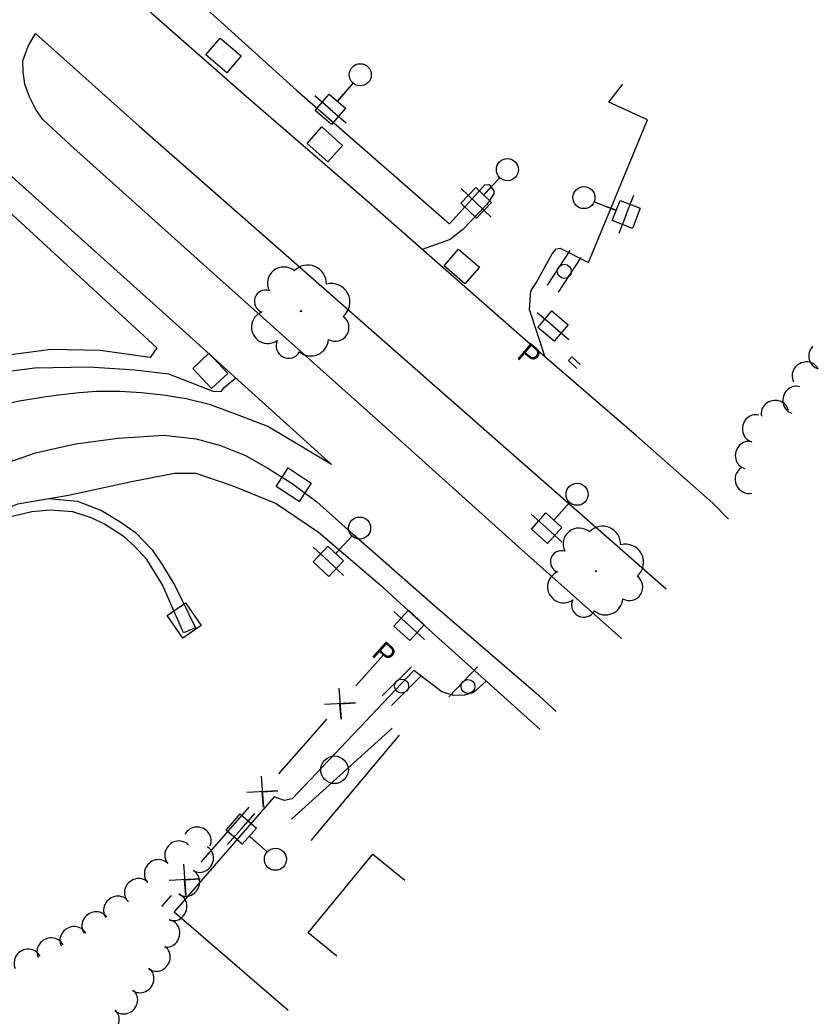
# Model space of a CAD drawing. Extents: x 1746010 to 1754829, y 655801 to 663091.
# Drawn here: x 1754540 to 1754828.9, y 656558.2 to 656918.7 of the extents above; entities that cross this region are included whole.
import ezdxf

# ---------------------------------------------------------------- set-up
doc = ezdxf.new("R2010")
doc.units = 0
for name, color, linetype in [('SURVEY - AERIAL SURVEY - Photo Control - Points - Elevations', 7, 'Continuous'), ('SURVEY - AERIAL SURVEY - Photo Control - Points - Locators', 7, 'Continuous'), ('SURVEY - AERIAL SURVEY - Photo Control with Text', 7, 'Continuous'), ('SURVEY - CENTERLINE - Existing Roads - Development', 7, 'Continuous'), ('SURVEY - CENTERLINE - Existing Roads Curve Text', 7, 'Continuous'), ('SURVEY - CENTERLINE - Existing Roads Text', 7, 'Continuous'), ('SURVEY - CENTERLINE - Preliminary - Development', 7, 'Continuous')]:
    doc.layers.add(name, color=color, linetype=linetype)

msp = doc.modelspace()

# ---------------------------------------------------------------- linework, layer by layer
at = {"layer": 'SURVEY - AERIAL SURVEY - Photo Control - Points - Elevations'}
for points in [[(1754741.64, 656792.56), (1754738.61, 656795.45), (1754739.83, 656796.72), (1754742.83, 656793.98)], [(1754550.39, 656745.47), (1754560.92, 656744.56), (1754569.61, 656741.2), (1754576.59, 656737.01), (1754581.85, 656733.17), (1754587.85, 656726.9), (1754591.59, 656721.34), (1754596.16, 656714.07), (1754603.59, 656698.7), (1754599.27, 656696.86), (1754591.65, 656714.3), (1754585.99, 656723.46), (1754581.44, 656728.39), (1754577.71, 656731.61), (1754570.64, 656736.24), (1754566.2, 656738.38), (1754559.15, 656740.67), (1754551.03, 656741.33), (1754544.35, 656740.64), (1754535.62, 656738.59)]]:
    msp.add_lwpolyline(points, dxfattribs=at)
at = {"layer": 'SURVEY - AERIAL SURVEY - Photo Control - Points - Locators'}
for points in [[(1754796.56, 656738.08), (1754790.79, 656743.77), (1754763.21, 656768.22), (1754722.88, 656802.95), (1754666.41, 656852.52), (1754621.07, 656891.69), (1754588.26, 656920.54), (1754581.81, 656926.89), (1754576.84, 656932.85), (1754573.4, 656937.61), (1754569.31, 656945.5), (1754567.71, 656950.42), (1754566.71, 656958.02), (1754566.56, 656966.03), (1754567.44, 656980.31), (1754571.26, 657001.16), (1754577.86, 657026.55), (1754586.05, 657050.51), (1754591.49, 657064.7), (1754606.23, 657097.49), (1754608.53, 657102.38)], [(1754566.62, 656967.04), (1754578.1, 656974.24), (1754587.27, 656976.38), (1754597.53, 656965.39), (1754600.9, 656960.46), (1754602.11, 656955.79), (1754601.33, 656951.64), (1754599.11, 656947.66), (1754590.27, 656938.32), (1754640.23, 656893.15), (1754695.52, 656844.87), (1754708.29, 656859.01), (1754709.91, 656859.11), (1754711.54, 656856.88), (1754711.55, 656855.7), (1754709.06, 656851.9), (1754700.4, 656842.83), (1754695.74, 656839.29), (1754685.63, 656835.65)], [(1754757.83, 656694.9), (1754721.68, 656726.94), (1754671.32, 656772.3), (1754610.07, 656826.93), (1754558.32, 656873.39), (1754548.36, 656882.63), (1754545.73, 656886.28), (1754543.51, 656890.83), (1754541.86, 656895.38), (1754541.15, 656899.9), (1754541.03, 656903.83), (1754542.96, 656909.13), (1754545.61, 656913.76), (1754583.25, 656880.21), (1754650.13, 656821.51), (1754710.03, 656768.93), (1754773.93, 656712.85)], [(1754730.17, 656796.68), (1754724.48, 656813.85), (1754724.97, 656820.52), (1754726.93, 656823.5), (1754732.7, 656834.08), (1754734.22, 656835.8), (1754735.56, 656836.08), (1754745.78, 656830.94), (1754767.17, 656882.52), (1754753.16, 656888.98), (1754758.28, 656895.43)], [(1754491.26, 656782.28), (1754505.51, 656831.98), (1754517.14, 656872.99), (1754517.76, 656873.93), (1754518.56, 656874.56), (1754520.31, 656874.58), (1754522.01, 656874.23), (1754525.07, 656872.42), (1754527.86, 656870.2), (1754600.07, 656805.5), (1754652.77, 656757.83), (1754629.75, 656771.57), (1754620.36, 656775.21), (1754609, 656779.38)], [(1754515.7, 656867.91), (1754589.54, 656800.08), (1754587.23, 656796.55), (1754569.07, 656799.11), (1754551.39, 656799.43), (1754533.09, 656797.03), (1754516.71, 656792.21), (1754507, 656788.08), (1754496.47, 656781.75)], [(1754492.67, 656787.2), (1754494.59, 656783.38), (1754498.31, 656780.16), (1754500.66, 656779.01), (1754504.27, 656779.76), (1754517.66, 656786.54), (1754531.06, 656790.97), (1754545.48, 656792.8), (1754565.15, 656793.13), (1754581.58, 656792.08), (1754593.86, 656790.64), (1754610.24, 656784.18), (1754613.03, 656784.3), (1754613.92, 656785.66), (1754618.16, 656789.14)], [(1754609, 656779.38), (1754600.26, 656781.64), (1754591.83, 656782.92), (1754584.08, 656783.75), (1754576.29, 656784.23), (1754567.79, 656784.21), (1754561.48, 656783.71), (1754553.96, 656782.85), (1754548.73, 656782.23), (1754539.17, 656780.59), (1754532.28, 656778.92), (1754523, 656775.94), (1754514.52, 656772.43), (1754503.33, 656766.26), (1754495.18, 656760.6), (1754487.89, 656754.77), (1754481, 656748.09), (1754474.66, 656740.47), (1754486.57, 656768.95), (1754491.27, 656782.33)], [(1754527.99, 656755.88), (1754545.71, 656762.02), (1754560.19, 656765.26), (1754575.61, 656767.31), (1754592.17, 656768.42), (1754603.86, 656767.12), (1754612.65, 656764.64), (1754621.68, 656761.04), (1754629.73, 656756.53), (1754638.59, 656750.92), (1754647.55, 656744.27), (1754657.69, 656735.31), (1754690.36, 656706.55), (1754726.59, 656675.27), (1754734.11, 656668.46)], [(1754393.05, 656531.8), (1754423.33, 656582.73), (1754448.6, 656628.4), (1754479.45, 656686.73), (1754490.32, 656704.5), (1754500.96, 656717.75), (1754511.34, 656728.84), (1754517.89, 656733.49), (1754529.75, 656739.72), (1754539.28, 656743.58), (1754557.66, 656746.7), (1754580.36, 656751.66), (1754595.94, 656754.66), (1754603.7, 656754.63), (1754617.08, 656750.14), (1754632.74, 656743.76), (1754648.07, 656733.32), (1754670.32, 656714.46), (1754689.22, 656697.01), (1754728.3, 656661.98)], [(1754708.79, 656679.47), (1754704.24, 656675.34), (1754700.91, 656674.41), (1754696.94, 656674.29), (1754692.69, 656675.52), (1754682.63, 656683.29), (1754638.54, 656636.79), (1754635.84, 656636.23), (1754632.05, 656637.55), (1754595.85, 656595.98), (1754637.18, 656560.4)]]:
    msp.add_lwpolyline(points, dxfattribs=at)
at = {"layer": 'SURVEY - AERIAL SURVEY - Photo Control with Text'}
for p, q in [((1754730.95, 656822.76), (1754739.18, 656835.31)), ((1754734.97, 656820.13), (1754743.19, 656832.68)), ((1754671.15, 656674.07), (1754681.79, 656684.66)), ((1754695.23, 656673.73), (1754705.6, 656684.57)), ((1754674.54, 656670.67), (1754685.17, 656681.25)), ((1754638.36, 656629.52), (1754674.71, 656662.44)), ((1754677.34, 656659.93), (1754645.36, 656621.82)), ((1754653.91, 656647.31), (1754653.91, 656647.31))]:
    msp.add_line(p, q, dxfattribs=at)
for centre, radius in [((1754737.07, 656827.72), 2.54), ((1754678.16, 656677.66), 2.54), ((1754702.21, 656677.48), 2.5), ((1754653.9, 656647.35), 5)]:
    msp.add_circle(centre, radius, dxfattribs=at)
at = {"layer": 'SURVEY - CENTERLINE - Existing Roads - Development'}
for points in [[(1754671.59, 656688.97), (1754661.67, 656677.72)], [(1754655.49, 656676.91), (1754656.26, 656665.69), (1754655.84, 656671.26), (1754661.49, 656671.62), (1754650.26, 656670.98)], [(1754651.03, 656665.65), (1754643.49, 656657.1)], [(1754643.49, 656657.1), (1754633.57, 656645.85)], [(1754627.39, 656645.04), (1754628.17, 656633.82), (1754627.74, 656639.39), (1754633.39, 656639.74), (1754622.17, 656639.11)], [(1754622.93, 656633.78), (1754615.39, 656625.23)], [(1754615.39, 656625.23), (1754605.47, 656613.98)], [(1754654.69, 656579.92), (1754644.36, 656588.42), (1754667.76, 656616.86), (1754679.3, 656607.36)], [(1754599.29, 656613.16), (1754600.07, 656601.95), (1754599.65, 656607.52), (1754605.29, 656607.87), (1754594.07, 656607.24)], [(1754594.83, 656601.9), (1754591.24, 656597.84)]]:
    msp.add_lwpolyline(points, dxfattribs=at)
at = {"layer": 'SURVEY - CENTERLINE - Existing Roads Curve Text'}
for p, q in [((1754660.65, 656895.87), (1754654.98, 656889.27)), ((1754655.24, 656889.57), (1754657.32, 656892)), ((1754652.43, 656886.31), (1754646.75, 656891.2)), ((1754652.43, 656886.31), (1754658.12, 656881.42)), ((1754713.82, 656861.68), (1754707.86, 656855.34)), ((1754705.19, 656852.51), (1754699.72, 656857.65)), ((1754708.13, 656855.64), (1754710.33, 656857.97)), ((1754705.19, 656852.51), (1754710.65, 656847.36)), ((1754747.79, 656852.96), (1754755.88, 656849.77)), ((1754759.51, 656848.33), (1754762.27, 656855.31)), ((1754755.51, 656849.91), (1754752.54, 656851.09)), ((1754759.51, 656848.33), (1754756.75, 656841.36)), ((1754732.99, 656807.88), (1754727.25, 656812.71)), ((1754732.99, 656807.88), (1754738.73, 656803.05)), ((1754739.11, 656744.15), (1754733.3, 656737.68)), ((1754730.69, 656734.77), (1754725.11, 656739.79)), ((1754733.57, 656737.97), (1754735.71, 656740.35)), ((1754730.69, 656734.77), (1754736.28, 656729.76)), ((1754660.3, 656731.97), (1754654.34, 656725.64)), ((1754651.67, 656722.8), (1754646.21, 656727.94)), ((1754654.61, 656725.93), (1754656.81, 656728.26)), ((1754651.67, 656722.8), (1754657.13, 656717.66)), ((1754680.88, 656699.59), (1754675.33, 656704.64)), ((1754680.88, 656699.59), (1754686.43, 656694.54)), ((1754620.15, 656625.92), (1754625.1, 656631.55)), ((1754620.15, 656625.92), (1754615.19, 656620.29)), ((1754629.6, 656617.59), (1754623.07, 656623.34)), ((1754623.37, 656623.08), (1754625.77, 656620.96))]:
    msp.add_line(p, q, dxfattribs=at)
for points in [[(1754646.93, 656885.9), (1754652.02, 656891.81), (1754657.93, 656886.73), (1754652.85, 656880.81)], [(1754699.67, 656852.34), (1754705.02, 656858.02), (1754710.7, 656852.67), (1754705.35, 656846.99)], [(1754761.7, 656843.27), (1754754.45, 656846.14), (1754757.32, 656853.39), (1754764.57, 656850.53)], [(1754732.52, 656813.38), (1754738.49, 656808.35), (1754733.46, 656802.39), (1754727.5, 656807.41)], [(1754725.19, 656734.48), (1754730.4, 656740.28), (1754736.2, 656735.07), (1754730.99, 656729.27)], [(1754646.15, 656722.63), (1754651.5, 656728.31), (1754657.18, 656722.96), (1754651.83, 656717.28)], [(1754680.62, 656705.1), (1754686.39, 656699.85), (1754681.14, 656694.08), (1754675.37, 656699.33)], [(1754619.8, 656631.42), (1754625.65, 656626.27), (1754620.49, 656620.41), (1754614.64, 656625.57)]]:
    msp.add_lwpolyline(points, close=True, dxfattribs=at)
for centre in [(1754663.19, 656898.82), (1754716.49, 656864.52), (1754744.16, 656854.4), (1754741.72, 656747.05), (1754662.98, 656734.81), (1754632.53, 656615.01)]:
    msp.add_circle(centre, 4, dxfattribs=at)
at = {"layer": 'SURVEY - CENTERLINE - Existing Roads Text'}
for centre, radius in [((1754641.77, 656813.3), 0.207), ((1754748.5, 656719.21), 0.202)]:
    msp.add_circle(centre, radius, dxfattribs=at)
for centre, radius, start, end in [((1754635.52, 656823.35), 5.93, 49.6679, 206.4568), ((1754644.22, 656823.21), 6.75, 358.7207, 136.2449), ((1754628.94, 656816.85), 4.07, 71.7841, 250.5297), ((1754652.76, 656816.59), 6.71, 309.6165, 105.455), ((1754629.78, 656807.52), 5.91, 111.8048, 305.2245), ((1754654.19, 656807.37), 4.95, 239.8694, 54.8697), ((1754637.25, 656800.74), 4.5, 154.4234, 331.7426), ((1754645.34, 656803.48), 6.38, 229.7105, 356.5562), ((1754742.4, 656729.03), 5.79, 49.6679, 206.4568), ((1754750.89, 656728.89), 6.59, 358.7207, 136.2449), ((1754735.98, 656722.68), 3.97, 71.7841, 250.5297), ((1754759.23, 656722.43), 6.55, 309.6165, 105.455), ((1754736.8, 656713.57), 5.77, 111.8048, 305.2245), ((1754760.63, 656713.43), 4.83, 239.8694, 54.8697), ((1754744.09, 656706.96), 4.39, 154.4234, 331.7426), ((1754751.99, 656709.63), 6.23, 229.7105, 356.5562)]:
    msp.add_arc(centre, radius, start, end, dxfattribs=at)
for centre, major_axis, start_param, end_param in [((1754830.3, 656797.26), (1.37, 4.81), 1.101437, 3.141593), ((1754824.44, 656790.18), (4.38, 2.41), 0, 3.141593), ((1754820.88, 656781.17), (1.49, 4.77), 0, 3.141593), ((1754813.3, 656776.29), (4.9, 1.02), 0, 3.141593), ((1754806.24, 656770.86), (1.28, 4.83), 0, 3.141593), ((1754803.68, 656761.19), (1.28, 4.83), 0, 3.141593), ((1754803.64, 656752.26), (-2.51, 4.32), 0, 2.876105), ((1754604.34, 656621.89), (4.56, -2.06), 0, 3.141593), ((1754597.3, 656616.77), (3.69, 3.37), 0, 3.141593), ((1754605.32, 656615.17), (-2.51, -4.33), 0, 3.141593), ((1754589.92, 656610.03), (3.69, 3.37), 0, 3.141593), ((1754600.32, 656606.53), (-2.5, -4.33), 0, 3.141593), ((1754582.7, 656603.16), (3.62, 3.45), 0, 3.141593), ((1754575.21, 656596.81), (4.07, 2.91), 0, 3.141593), ((1754595.74, 656597.73), (-1.75, -4.69), 0, 3.141593), ((1754567.37, 656591.2), (4.07, 2.91), 0, 3.141593), ((1754593.2, 656588.19), (-0.85, -4.93), 0, 3.141593), ((1754559.44, 656585.86), (4.49, 2.21), 0, 3.141593), ((1754551.14, 656581.77), (4.49, 2.21), 0, 3.141593), ((1754542.84, 656577.68), (4.49, 2.21), 0, 3.141593), ((1754589.63, 656579.33), (-3.02, -3.98), 0, 3.141593), ((1754583.74, 656571.58), (-3.02, -3.98), 0, 3.141593), ((1754577.83, 656563.85), (-3.42, -3.64), 0, 3.141593), ((1754571.16, 656556.76), (-3.42, -3.64), 0, 3.141593)]:
    msp.add_ellipse(centre, major_axis=major_axis, ratio=0.940188, start_param=start_param, end_param=end_param, dxfattribs=at)
at = {"layer": 'SURVEY - CENTERLINE - Preliminary - Development'}
for p, q in [((1754613.71, 656905.83), (1754613.71, 656905.83)), ((1754650.37, 656873.63), (1754650.37, 656873.63)), ((1754699.93, 656829.49), (1754699.93, 656829.49)), ((1754608.92, 656791.66), (1754608.92, 656791.66)), ((1754639.09, 656750.49), (1754639.09, 656750.49)), ((1754599.51, 656701.37), (1754599.51, 656701.37))]:
    msp.add_line(p, q, dxfattribs=at)
for points in [[(1754607.31, 656906.02), (1754612.49, 656912.11), (1754620.11, 656905.64), (1754614.93, 656899.54), (1754607.31, 656906.02)], [(1754643.98, 656873.97), (1754649.3, 656879.95), (1754656.77, 656873.3), (1754651.45, 656867.32), (1754643.98, 656873.97)], [(1754693.53, 656829.73), (1754698.75, 656835.79), (1754706.32, 656829.25), (1754701.1, 656823.2), (1754693.53, 656829.73)], [(1754602.58, 656792.58), (1754608.42, 656798.05), (1754615.25, 656790.74), (1754609.41, 656785.28), (1754602.58, 656792.58)], [(1754632.72, 656749.88), (1754637.1, 656756.57), (1754645.47, 656751.09), (1754641.08, 656744.4), (1754632.72, 656749.88)], [(1754593.38, 656703.24), (1754599.99, 656707.76), (1754605.63, 656699.51), (1754599.03, 656694.99), (1754593.38, 656703.24)]]:
    msp.add_lwpolyline(points, dxfattribs=at)

# ---------------------------------------------------------------- texts
at = {"layer": 'SURVEY - CENTERLINE - Existing Roads Curve Text'}
for rotation, p in [(319.9135, (1754719.48, 656796.64)), (317.7122, (1754666.95, 656688.88))]:
    msp.add_text('P', height=7.48, rotation=rotation, dxfattribs=at).set_placement(p)

doc.saveas('drawing.dxf')
